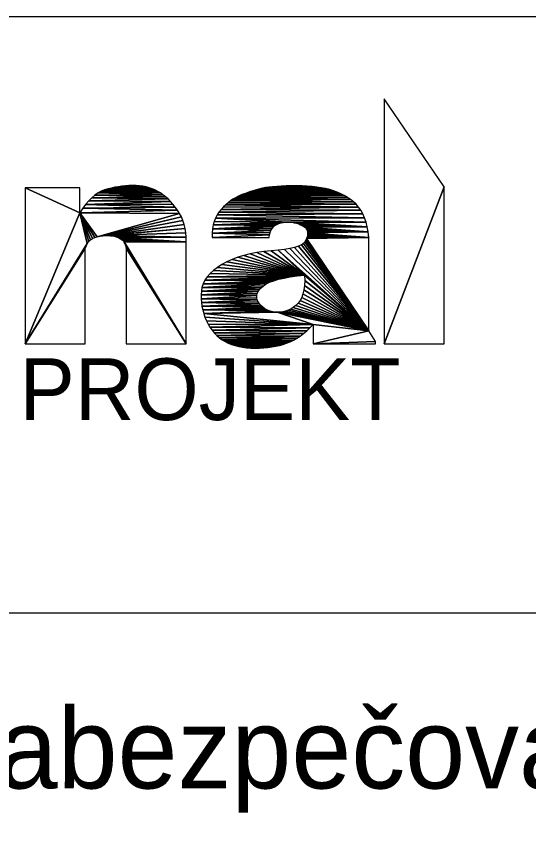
# Model space of a CAD drawing. Extents: x -1424 to 5155, y -2900 to 2050.
# Drawn here: x 2999.7 to 3018.76, y -2318.39 to -2287.77 of the extents above; entities that cross this region are included whole.
import ezdxf

# ---------------------------------------------------------------- set-up
doc = ezdxf.new("R2010")
doc.units = 0
doc.layers.add('Vrstva 1', color=7, linetype='Continuous')

msp = doc.modelspace()

# ---------------------------------------------------------------- linework, layer by layer
for points in [[(2980, -2287.774), (3145, -2287.774), (3145, -2340), (2980, -2340)], [(3013.38, -2290.842), (3013.38, -2299.962), (3015.62, -2294.122)], [(3002.06, -2295.082), (3002.06, -2294.162), (3000.02, -2294.162)], [(3000.02, -2294.162), (3000.02, -2299.962), (3002.06, -2295.082)], [(3002.858, -2294.284), (3002.737, -2294.348), (3004.956, -2294.288)], [(3004.956, -2294.288), (3002.737, -2294.348), (3005.056, -2294.346)], [(3004.854, -2294.236), (3002.858, -2294.284), (3004.956, -2294.288)], [(3002.982, -2294.236), (3002.858, -2294.284), (3004.854, -2294.236)], [(3003.108, -2294.198), (3002.982, -2294.236), (3004.854, -2294.236)], [(3003.234, -2294.164), (3003.108, -2294.198), (3004.748, -2294.192)], [(3004.748, -2294.192), (3003.108, -2294.198), (3004.854, -2294.236)], [(3003.362, -2294.136), (3003.234, -2294.164), (3004.637, -2294.154)], [(3004.637, -2294.154), (3003.234, -2294.164), (3004.748, -2294.192)], [(3003.491, -2294.114), (3003.362, -2294.136), (3004.522, -2294.124)], [(3004.522, -2294.124), (3003.362, -2294.136), (3004.637, -2294.154)], [(3003.621, -2294.096), (3003.491, -2294.114), (3004.403, -2294.1)], [(3004.403, -2294.1), (3003.491, -2294.114), (3004.522, -2294.124)], [(3003.753, -2294.082), (3003.621, -2294.096), (3004.279, -2294.084)], [(3004.279, -2294.084), (3003.621, -2294.096), (3004.403, -2294.1)], [(3003.885, -2294.074), (3003.753, -2294.082), (3004.279, -2294.084)], [(3004.019, -2294.072), (3003.885, -2294.074), (3004.151, -2294.074)], [(3004.151, -2294.074), (3003.885, -2294.074), (3004.279, -2294.084)], [(3008.405, -2294.298), (3008.313, -2294.328), (3011.642, -2294.318)], [(3011.642, -2294.318), (3008.313, -2294.328), (3011.774, -2294.376)], [(3008.495, -2294.268), (3008.405, -2294.298), (3011.642, -2294.318)], [(3008.585, -2294.24), (3008.495, -2294.268), (3011.503, -2294.266)], [(3011.503, -2294.266), (3008.495, -2294.268), (3011.642, -2294.318)], [(3008.675, -2294.214), (3008.585, -2294.24), (3011.358, -2294.222)], [(3011.358, -2294.222), (3008.585, -2294.24), (3011.503, -2294.266)], [(3008.763, -2294.19), (3008.675, -2294.214), (3011.358, -2294.222)], [(3008.859, -2294.168), (3008.763, -2294.19), (3011.206, -2294.184)], [(3011.206, -2294.184), (3008.763, -2294.19), (3011.358, -2294.222)], [(3008.97, -2294.15), (3008.859, -2294.168), (3011.047, -2294.152)], [(3011.047, -2294.152), (3008.859, -2294.168), (3011.206, -2294.184)], [(3009.095, -2294.132), (3008.97, -2294.15), (3011.047, -2294.152)], [(3009.234, -2294.118), (3009.095, -2294.132), (3010.881, -2294.126)], [(3010.881, -2294.126), (3009.095, -2294.132), (3011.047, -2294.152)], [(3009.389, -2294.104), (3009.234, -2294.118), (3010.707, -2294.106)], [(3010.707, -2294.106), (3009.234, -2294.118), (3010.881, -2294.126)], [(3009.558, -2294.094), (3009.389, -2294.104), (3010.707, -2294.106)], [(3009.742, -2294.086), (3009.558, -2294.094), (3010.526, -2294.09)], [(3010.526, -2294.09), (3009.558, -2294.094), (3010.707, -2294.106)], [(3009.941, -2294.08), (3009.742, -2294.086), (3010.339, -2294.082)], [(3010.339, -2294.082), (3009.742, -2294.086), (3010.526, -2294.09)], [(3010.143, -2294.078), (3009.941, -2294.08), (3010.339, -2294.082)], [(3015.62, -2294.122), (3013.38, -2299.962), (3015.62, -2299.962)], [(3002.502, -2294.528), (3002.388, -2294.642), (3005.341, -2294.572)], [(3005.341, -2294.572), (3002.388, -2294.642), (3005.432, -2294.664)], [(3002.618, -2294.43), (3002.502, -2294.528), (3005.248, -2294.488)], [(3005.248, -2294.488), (3002.502, -2294.528), (3005.341, -2294.572)], [(3002.737, -2294.348), (3002.618, -2294.43), (3005.153, -2294.414)], [(3005.153, -2294.414), (3002.618, -2294.43), (3005.248, -2294.488)], [(3005.056, -2294.346), (3002.737, -2294.348), (3005.153, -2294.414)], [(3007.758, -2294.58), (3007.668, -2294.642), (3012.134, -2294.592)], [(3012.134, -2294.592), (3007.668, -2294.642), (3012.241, -2294.678)], [(3007.85, -2294.524), (3007.758, -2294.58), (3012.134, -2294.592)], [(3007.942, -2294.476), (3007.85, -2294.524), (3012.02, -2294.514)], [(3012.02, -2294.514), (3007.85, -2294.524), (3012.134, -2294.592)], [(3008.035, -2294.434), (3007.942, -2294.476), (3011.9, -2294.442)], [(3011.9, -2294.442), (3007.942, -2294.476), (3012.02, -2294.514)], [(3008.129, -2294.398), (3008.035, -2294.434), (3011.9, -2294.442)], [(3008.221, -2294.362), (3008.129, -2294.398), (3011.774, -2294.376)], [(3011.774, -2294.376), (3008.129, -2294.398), (3011.9, -2294.442)], [(3008.313, -2294.328), (3008.221, -2294.362), (3011.774, -2294.376)], [(3002.167, -2294.918), (3002.06, -2295.082), (3005.692, -2294.988)], [(3002.276, -2294.772), (3002.167, -2294.918), (3005.607, -2294.872)], [(3005.607, -2294.872), (3002.167, -2294.918), (3005.692, -2294.988)], [(3002.388, -2294.642), (3002.276, -2294.772), (3005.432, -2294.664)], [(3005.432, -2294.664), (3002.276, -2294.772), (3005.521, -2294.764)], [(3005.521, -2294.764), (3002.276, -2294.772), (3005.607, -2294.872)], [(3007.404, -2294.87), (3007.318, -2294.96), (3012.435, -2294.874)], [(3012.435, -2294.874), (3007.318, -2294.96), (3012.519, -2294.992)], [(3007.491, -2294.788), (3007.404, -2294.87), (3012.435, -2294.874)], [(3007.579, -2294.712), (3007.491, -2294.788), (3012.342, -2294.77)], [(3012.342, -2294.77), (3007.491, -2294.788), (3012.435, -2294.874)], [(3007.668, -2294.642), (3007.579, -2294.712), (3012.241, -2294.678)], [(3012.241, -2294.678), (3007.579, -2294.712), (3012.342, -2294.77)], [(3002.06, -2295.082), (3000.02, -2299.962), (3002.338, -2296.23)], [(3005.692, -2294.988), (3002.06, -2295.082), (3005.771, -2295.112)], [(3002.06, -2295.082), (3002.709, -2295.976), (3005.771, -2295.112)], [(3002.06, -2295.082), (3002.615, -2296.006), (3002.709, -2295.976)], [(3002.06, -2295.082), (3002.531, -2296.048), (3002.615, -2296.006)], [(3002.06, -2295.082), (3002.457, -2296.098), (3002.531, -2296.048)], [(3002.06, -2295.082), (3002.393, -2296.16), (3002.457, -2296.098)], [(3002.06, -2295.082), (3002.338, -2296.23), (3002.393, -2296.16)], [(3005.771, -2295.112), (3002.709, -2295.976), (3005.839, -2295.242)], [(3005.839, -2295.242), (3002.709, -2295.976), (3002.813, -2295.954)], [(3005.839, -2295.242), (3002.813, -2295.954), (3005.896, -2295.378)], [(3007.168, -2295.164), (3007.11, -2295.28), (3012.657, -2295.27)], [(3007.237, -2295.058), (3007.168, -2295.164), (3012.593, -2295.124)], [(3012.593, -2295.124), (3007.168, -2295.164), (3012.657, -2295.27)], [(3007.318, -2294.96), (3007.237, -2295.058), (3012.519, -2294.992)], [(3012.519, -2294.992), (3007.237, -2295.058), (3012.593, -2295.124)], [(3005.896, -2295.378), (3002.813, -2295.954), (3005.942, -2295.522)], [(3005.942, -2295.522), (3002.813, -2295.954), (3002.919, -2295.942)], [(3005.942, -2295.522), (3002.919, -2295.942), (3005.978, -2295.672)], [(3007.025, -2295.54), (3006.999, -2295.686), (3009.322, -2295.562)], [(3007.062, -2295.406), (3007.025, -2295.54), (3009.791, -2295.43)], [(3009.791, -2295.43), (3007.025, -2295.54), (3009.709, -2295.434)], [(3009.709, -2295.434), (3007.025, -2295.54), (3009.627, -2295.446)], [(3009.627, -2295.446), (3007.025, -2295.54), (3009.546, -2295.464)], [(3009.546, -2295.464), (3007.025, -2295.54), (3009.465, -2295.488)], [(3009.465, -2295.488), (3007.025, -2295.54), (3009.389, -2295.52)], [(3009.389, -2295.52), (3007.025, -2295.54), (3009.322, -2295.562)], [(3007.11, -2295.28), (3007.062, -2295.406), (3009.791, -2295.43)], [(3012.657, -2295.27), (3007.11, -2295.28), (3012.712, -2295.432)], [(3007.11, -2295.28), (3009.791, -2295.43), (3012.712, -2295.432)], [(3009.791, -2295.43), (3009.873, -2295.432), (3012.712, -2295.432)], [(3009.873, -2295.432), (3009.956, -2295.44), (3012.712, -2295.432)], [(3012.712, -2295.432), (3009.956, -2295.44), (3012.757, -2295.608)], [(3009.956, -2295.44), (3010.04, -2295.454), (3012.757, -2295.608)], [(3010.04, -2295.454), (3010.124, -2295.476), (3012.757, -2295.608)], [(3010.124, -2295.476), (3010.204, -2295.502), (3012.757, -2295.608)], [(3010.204, -2295.502), (3010.276, -2295.53), (3012.757, -2295.608)], [(3010.276, -2295.53), (3010.338, -2295.56), (3012.757, -2295.608)], [(3005.978, -2295.672), (3002.919, -2295.942), (3003.02, -2295.934)], [(3005.978, -2295.672), (3003.02, -2295.934), (3003.115, -2295.934)], [(3005.978, -2295.672), (3003.115, -2295.934), (3006.002, -2295.83)], [(3006.002, -2295.83), (3003.115, -2295.934), (3006.016, -2295.992)], [(3006.984, -2295.84), (3006.98, -2296.002), (3009.115, -2295.906)], [(3006.999, -2295.686), (3006.984, -2295.84), (3009.172, -2295.74)], [(3009.172, -2295.74), (3006.984, -2295.84), (3009.139, -2295.818)], [(3009.139, -2295.818), (3006.984, -2295.84), (3009.115, -2295.906)], [(3009.322, -2295.562), (3006.999, -2295.686), (3009.263, -2295.612)], [(3009.263, -2295.612), (3006.999, -2295.686), (3009.213, -2295.672)], [(3009.213, -2295.672), (3006.999, -2295.686), (3009.172, -2295.74)], [(3010.338, -2295.56), (3010.392, -2295.592), (3012.757, -2295.608)], [(3010.392, -2295.592), (3010.437, -2295.626), (3012.757, -2295.608)], [(3012.757, -2295.608), (3010.437, -2295.626), (3012.793, -2295.798)], [(3010.437, -2295.626), (3010.474, -2295.662), (3012.793, -2295.798)], [(3010.474, -2295.662), (3010.501, -2295.7), (3012.793, -2295.798)], [(3010.501, -2295.7), (3010.52, -2295.74), (3012.793, -2295.798)], [(3010.52, -2295.74), (3010.532, -2295.784), (3012.793, -2295.798)], [(3010.532, -2295.784), (3010.537, -2295.83), (3012.793, -2295.798)], [(3010.537, -2295.83), (3010.536, -2295.878), (3012.82, -2296.002)], [(3012.793, -2295.798), (3010.537, -2295.83), (3012.82, -2296.002)], [(3003.115, -2295.934), (3003.206, -2295.938), (3006.016, -2295.992)], [(3003.206, -2295.938), (3003.291, -2295.95), (3006.016, -2295.992)], [(3003.291, -2295.95), (3003.37, -2295.968), (3006.016, -2295.992)], [(3003.37, -2295.968), (3003.445, -2295.992), (3006.016, -2295.992)], [(3003.445, -2295.992), (3003.514, -2296.022), (3006.016, -2295.992)], [(3006.016, -2295.992), (3003.514, -2296.022), (3006.02, -2296.162)], [(3003.514, -2296.022), (3003.576, -2296.056), (3006.02, -2296.162)], [(3003.576, -2296.056), (3003.63, -2296.094), (3006.02, -2296.162)], [(3003.63, -2296.094), (3003.676, -2296.136), (3006.02, -2296.162)], [(3003.676, -2296.136), (3003.713, -2296.182), (3006.02, -2296.162)], [(3006.02, -2296.162), (3003.713, -2296.182), (3006.02, -2299.962)], [(3009.115, -2295.906), (3006.98, -2296.002), (3009.1, -2296.002)], [(3010.436, -2296.162), (3010.385, -2296.224), (3012.82, -2299.482)], [(3010.468, -2296.1), (3010.436, -2296.162), (3012.82, -2299.482)], [(3010.494, -2296.04), (3010.468, -2296.1), (3012.82, -2299.482)], [(3010.514, -2295.984), (3010.494, -2296.04), (3012.82, -2296.002)], [(3012.82, -2296.002), (3010.494, -2296.04), (3012.82, -2299.482)], [(3010.528, -2295.93), (3010.514, -2295.984), (3012.82, -2296.002)], [(3010.536, -2295.878), (3010.528, -2295.93), (3012.82, -2296.002)], [(3002.338, -2296.23), (3000.02, -2299.962), (3002.294, -2296.312)], [(3002.294, -2296.312), (3000.02, -2299.962), (3002.26, -2296.402)], [(3002.26, -2296.402), (3000.02, -2299.962), (3002.26, -2299.962)], [(3003.713, -2296.182), (3003.742, -2296.232), (3006.02, -2299.962)], [(3003.742, -2296.232), (3003.763, -2296.284), (3006.02, -2299.962)], [(3003.763, -2296.284), (3003.775, -2296.342), (3006.02, -2299.962)], [(3003.775, -2296.342), (3003.78, -2296.402), (3006.02, -2299.962)], [(3003.78, -2296.402), (3003.78, -2299.962), (3006.02, -2299.962)], [(3009.677, -2296.45), (3009.444, -2296.48), (3012.82, -2299.482)], [(3009.879, -2296.416), (3009.677, -2296.45), (3012.82, -2299.482)], [(3010.051, -2296.376), (3009.879, -2296.416), (3012.82, -2299.482)], [(3010.193, -2296.33), (3010.051, -2296.376), (3012.82, -2299.482)], [(3010.304, -2296.28), (3010.193, -2296.33), (3012.82, -2299.482)], [(3010.385, -2296.224), (3010.304, -2296.28), (3012.82, -2299.482)], [(3007.945, -2296.744), (3007.734, -2296.824), (3010.424, -2297.406)], [(3008.167, -2296.674), (3007.945, -2296.744), (3010.424, -2297.406)], [(3008.402, -2296.616), (3008.167, -2296.674), (3010.424, -2297.406)], [(3008.65, -2296.568), (3008.402, -2296.616), (3010.424, -2297.406)], [(3008.909, -2296.532), (3008.65, -2296.568), (3010.424, -2297.406)], [(3009.181, -2296.504), (3008.909, -2296.532), (3010.424, -2297.406)], [(3009.444, -2296.48), (3009.181, -2296.504), (3010.424, -2297.406)], [(3009.444, -2296.48), (3010.424, -2297.406), (3012.82, -2299.482)], [(3007.35, -2297.014), (3007.181, -2297.122), (3010.424, -2297.406)], [(3007.536, -2296.914), (3007.35, -2297.014), (3010.424, -2297.406)], [(3007.734, -2296.824), (3007.536, -2296.914), (3010.424, -2297.406)], [(3006.905, -2297.352), (3006.799, -2297.474), (3010.424, -2297.406)], [(3007.033, -2297.234), (3006.905, -2297.352), (3010.424, -2297.406)], [(3007.181, -2297.122), (3007.033, -2297.234), (3010.424, -2297.406)], [(3006.713, -2297.6), (3006.648, -2297.73), (3009.277, -2297.616)], [(3009.277, -2297.616), (3006.648, -2297.73), (3009.124, -2297.674)], [(3009.124, -2297.674), (3006.648, -2297.73), (3008.995, -2297.736)], [(3009.89, -2297.474), (3006.713, -2297.6), (3009.661, -2297.516)], [(3006.799, -2297.474), (3006.713, -2297.6), (3009.89, -2297.474)], [(3009.661, -2297.516), (3006.713, -2297.6), (3009.456, -2297.564)], [(3009.456, -2297.564), (3006.713, -2297.6), (3009.277, -2297.616)], [(3010.424, -2297.406), (3006.799, -2297.474), (3010.145, -2297.438)], [(3010.145, -2297.438), (3006.799, -2297.474), (3009.89, -2297.474)], [(3010.429, -2297.606), (3010.42, -2297.788), (3012.82, -2299.482)], [(3010.424, -2297.406), (3010.429, -2297.606), (3012.82, -2299.482)], [(3006.604, -2297.866), (3006.581, -2298.006), (3008.809, -2297.876)], [(3008.809, -2297.876), (3006.581, -2298.006), (3008.743, -2297.948)], [(3008.743, -2297.948), (3006.581, -2298.006), (3008.694, -2298.022)], [(3006.648, -2297.73), (3006.604, -2297.866), (3008.995, -2297.736)], [(3008.995, -2297.736), (3006.604, -2297.866), (3008.892, -2297.804)], [(3008.892, -2297.804), (3006.604, -2297.866), (3008.809, -2297.876)], [(3010.398, -2297.954), (3010.364, -2298.102), (3012.82, -2299.482)], [(3010.42, -2297.788), (3010.398, -2297.954), (3012.82, -2299.482)], [(3006.581, -2298.006), (3006.573, -2298.146), (3008.694, -2298.022)], [(3008.694, -2298.022), (3006.573, -2298.146), (3008.662, -2298.096)], [(3008.662, -2298.096), (3006.573, -2298.146), (3008.646, -2298.172)], [(3006.573, -2298.146), (3006.574, -2298.286), (3008.646, -2298.172)], [(3008.646, -2298.172), (3006.574, -2298.286), (3008.647, -2298.248)], [(3008.647, -2298.248), (3006.574, -2298.286), (3008.665, -2298.324)], [(3006.574, -2298.286), (3006.584, -2298.426), (3008.665, -2298.324)], [(3010.316, -2298.236), (3010.256, -2298.354), (3012.82, -2299.482)], [(3010.364, -2298.102), (3010.316, -2298.236), (3012.82, -2299.482)], [(3008.665, -2298.324), (3006.584, -2298.426), (3008.699, -2298.402)], [(3008.699, -2298.402), (3006.584, -2298.426), (3008.746, -2298.476)], [(3006.584, -2298.426), (3006.603, -2298.564), (3008.746, -2298.476)], [(3008.746, -2298.476), (3006.603, -2298.564), (3008.801, -2298.544)], [(3008.801, -2298.544), (3006.603, -2298.564), (3008.864, -2298.602)], [(3006.603, -2298.564), (3006.631, -2298.7), (3008.864, -2298.602)], [(3008.864, -2298.602), (3006.631, -2298.7), (3008.935, -2298.654)], [(3010.096, -2298.54), (3010.003, -2298.612), (3012.82, -2299.482)], [(3010.182, -2298.456), (3010.096, -2298.54), (3012.82, -2299.482)], [(3010.256, -2298.354), (3010.182, -2298.456), (3012.82, -2299.482)], [(3008.935, -2298.654), (3006.631, -2298.7), (3009.014, -2298.698)], [(3009.014, -2298.698), (3006.631, -2298.7), (3009.1, -2298.734)], [(3006.631, -2298.7), (3006.668, -2298.836), (3009.1, -2298.734)], [(3009.1, -2298.734), (3006.668, -2298.836), (3009.195, -2298.762)], [(3009.195, -2298.762), (3006.668, -2298.836), (3009.298, -2298.782)], [(3009.298, -2298.782), (3006.668, -2298.836), (3009.404, -2298.792)], [(3009.404, -2298.792), (3006.668, -2298.836), (3010.74, -2299.242)], [(3006.668, -2298.836), (3006.714, -2298.97), (3010.74, -2299.242)], [(3009.404, -2298.792), (3010.74, -2299.242), (3012.82, -2299.482)], [(3009.508, -2298.792), (3009.404, -2298.792), (3012.82, -2299.482)], [(3009.611, -2298.78), (3009.508, -2298.792), (3012.82, -2299.482)], [(3009.711, -2298.754), (3009.611, -2298.78), (3012.82, -2299.482)], [(3009.81, -2298.718), (3009.711, -2298.754), (3012.82, -2299.482)], [(3009.907, -2298.672), (3009.81, -2298.718), (3012.82, -2299.482)], [(3010.003, -2298.612), (3009.907, -2298.672), (3012.82, -2299.482)], [(3006.714, -2298.97), (3006.769, -2299.104), (3010.74, -2299.242)], [(3006.769, -2299.104), (3006.832, -2299.232), (3010.74, -2299.242)], [(3006.832, -2299.232), (3006.902, -2299.35), (3010.74, -2299.242)], [(3010.74, -2299.242), (3006.902, -2299.35), (3010.622, -2299.366)], [(3006.902, -2299.35), (3006.979, -2299.462), (3010.622, -2299.366)], [(3010.622, -2299.366), (3006.979, -2299.462), (3010.504, -2299.48)], [(3006.979, -2299.462), (3007.063, -2299.562), (3010.504, -2299.48)], [(3010.504, -2299.48), (3007.063, -2299.562), (3010.383, -2299.582)], [(3010.74, -2299.242), (3010.74, -2299.962), (3012.82, -2299.482)], [(3012.82, -2299.482), (3010.74, -2299.962), (3013.06, -2299.882)], [(3007.063, -2299.562), (3007.153, -2299.656), (3010.383, -2299.582)], [(3010.383, -2299.582), (3007.153, -2299.656), (3010.261, -2299.676)], [(3007.153, -2299.656), (3007.251, -2299.74), (3010.261, -2299.676)], [(3010.261, -2299.676), (3007.251, -2299.74), (3010.137, -2299.758)], [(3007.251, -2299.74), (3007.355, -2299.814), (3010.137, -2299.758)], [(3010.137, -2299.758), (3007.355, -2299.814), (3010.012, -2299.83)], [(3007.355, -2299.814), (3007.467, -2299.88), (3010.012, -2299.83)], [(3010.012, -2299.83), (3007.467, -2299.88), (3009.885, -2299.892)], [(3007.467, -2299.88), (3007.585, -2299.938), (3009.885, -2299.892)], [(3009.885, -2299.892), (3007.585, -2299.938), (3009.756, -2299.942)], [(3007.585, -2299.938), (3007.709, -2299.988), (3009.756, -2299.942)], [(3009.756, -2299.942), (3007.709, -2299.988), (3009.625, -2299.986)], [(3009.625, -2299.986), (3007.709, -2299.988), (3009.489, -2300.024)], [(3007.709, -2299.988), (3007.839, -2300.03), (3009.489, -2300.024)], [(3009.489, -2300.024), (3007.839, -2300.03), (3009.348, -2300.054)], [(3007.839, -2300.03), (3007.976, -2300.064), (3009.348, -2300.054)], [(3009.348, -2300.054), (3007.976, -2300.064), (3009.204, -2300.08)], [(3007.976, -2300.064), (3008.118, -2300.092), (3009.204, -2300.08)], [(3009.204, -2300.08), (3008.118, -2300.092), (3009.055, -2300.1)], [(3008.118, -2300.092), (3008.267, -2300.112), (3009.055, -2300.1)], [(3009.055, -2300.1), (3008.267, -2300.112), (3008.902, -2300.114)], [(3008.267, -2300.112), (3008.421, -2300.122), (3008.902, -2300.114)], [(3008.902, -2300.114), (3008.421, -2300.122), (3008.744, -2300.124)], [(3008.421, -2300.122), (3008.582, -2300.126), (3008.744, -2300.124)], [(3013.06, -2299.882), (3010.74, -2299.962), (3013.06, -2299.962)]]:
    msp.add_lwpolyline(points, close=True)
at = {"layer": 'Vrstva 1'}
msp.add_line((3095.12, -2310), (2980, -2310), dxfattribs=at)

# ---------------------------------------------------------------- texts
for s, height, p in [('PROJEKT', 2.299, (2999.82, -2302.806)), ('Oprava zabezpečovacího zařízení v ŽST Bystřice nad Pernštejnem', 3, (2982.725, -2316.524))]:
    msp.add_text(s, height=height).set_placement(p)

doc.saveas('drawing.dxf')
